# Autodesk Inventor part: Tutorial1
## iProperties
Shininess: 77.0
Length Units: 11269
Angle Units: 11279
Time Units: 11290
Mass Units: 11283
Length Display Precision: 3
Angle Display Precision: 2
Created: 2001-12
Part Number: Tutorial1
Document SubType Name: Modeling
Designer: Renu Muthoo
Density: 1 g/cm^3
Density: 0.0
Volumn: 0.0
Area: 0.0
PropertySet Name: Model Information
Control State: 0
Master: False
Checked Out: False
Author: Renu Muthoo
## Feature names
1. Extrusion1
2. Extrusion2
3. Fillet1
